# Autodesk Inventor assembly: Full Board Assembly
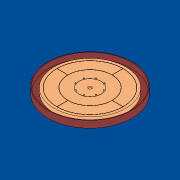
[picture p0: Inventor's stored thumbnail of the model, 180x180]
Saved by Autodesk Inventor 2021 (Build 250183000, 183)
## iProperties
Created: 2020-10
Part Number: Full Board Assembly
Document SubType Name: Assembly
Designer: Stu
Author: Stu
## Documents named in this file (4)
- C:\Users\Stu\Google Drive\Projects\CAD\Crokinole\Full Board Assembly.iam
- C:\Users\Stu\Google Drive\Projects\CAD\Crokinole\Board.ipt
- C:\Users\Stu\Google Drive\Projects\CAD\Crokinole\base.ipt
- C:\Users\Stu\Google Drive\Projects\CAD\Crokinole\pins.ipt
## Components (10 placed, 3 different names)
1. Board:1 — Mate:1, Flush:1, Flush:2, Mate:2, Mate:3, Mate:4, Mate:5
2. base:1 — Mate:2, Mate:3, Angle:1
3. pins:1 — Mate:4, Mate:5
4. pins:2
5. pins:3
6. pins:4
7. pins:5
8. pins:6
9. pins:7
10. pins:8
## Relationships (8: Mate 5, Flush 2, Angle 1)
- Mate:1: Board:1
- Flush:1: Board:1
- Flush:2: Board:1
- Mate:2: Board:1 ↔ base:1
- Mate:3: Board:1 ↔ base:1
- Angle:1: base:1
- Mate:4: Board:1 ↔ pins:1
- Mate:5: Board:1 ↔ pins:1
